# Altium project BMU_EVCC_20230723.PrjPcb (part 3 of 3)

## Sheet BMU_A1_bq79616.SchDoc
size 558 x 431 mm; Date: Not shown in title block; ApprovedBy: Not shown in title block; CheckedBy: Not shown in title block; Author: Not shown in title block; CompanyName: Not shown in title block; Engineer: Not shown in title block; Organization: Not shown in title block; Address1: Not shown in title block; Address2: Not shown in title block; Address3: Not shown in title block; Address4: Not shown in title block; DocumentNumber: 1; Revision: Use project parameter SCH_Rev; SheetNumber: 7; SheetTotal: 9; PageSetup: Record=PageOptions¦CenterHorizontal=True¦CenterVertical=True¦PrintScale=1.00¦XCorrection=1.00¦YCorrection=1.00¦PrintKind=0¦BorderSize=5000000¦LeftOffset=0¦BottomOffset=0¦Orientation=2¦PaperLength=1000¦PaperWidth=1000¦Scale=100¦PaperSource=15¦PrintQuality=600¦MediaType=1¦DitherType=10¦PaperKind=Letter¦PrintScaleMode=1
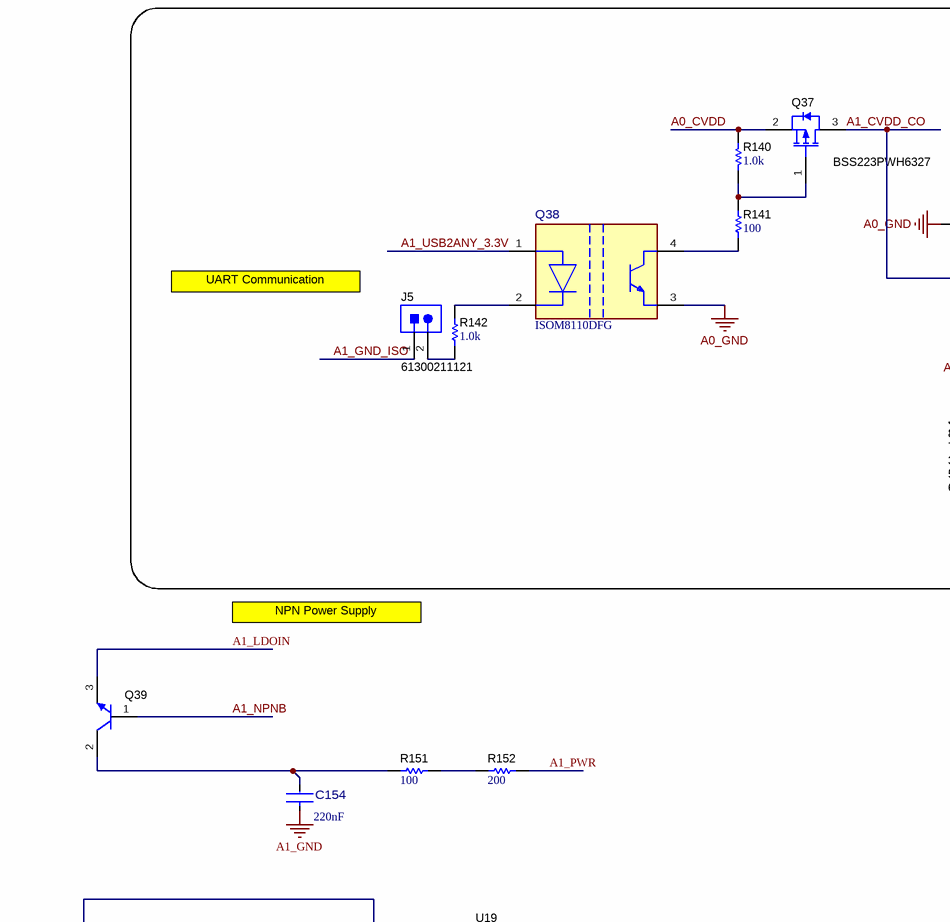
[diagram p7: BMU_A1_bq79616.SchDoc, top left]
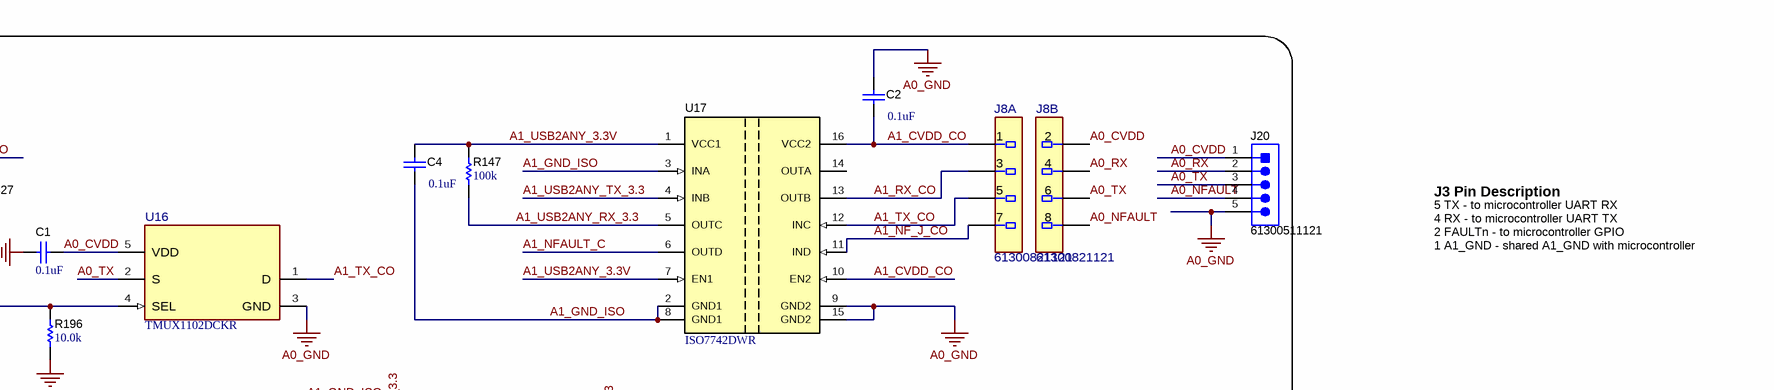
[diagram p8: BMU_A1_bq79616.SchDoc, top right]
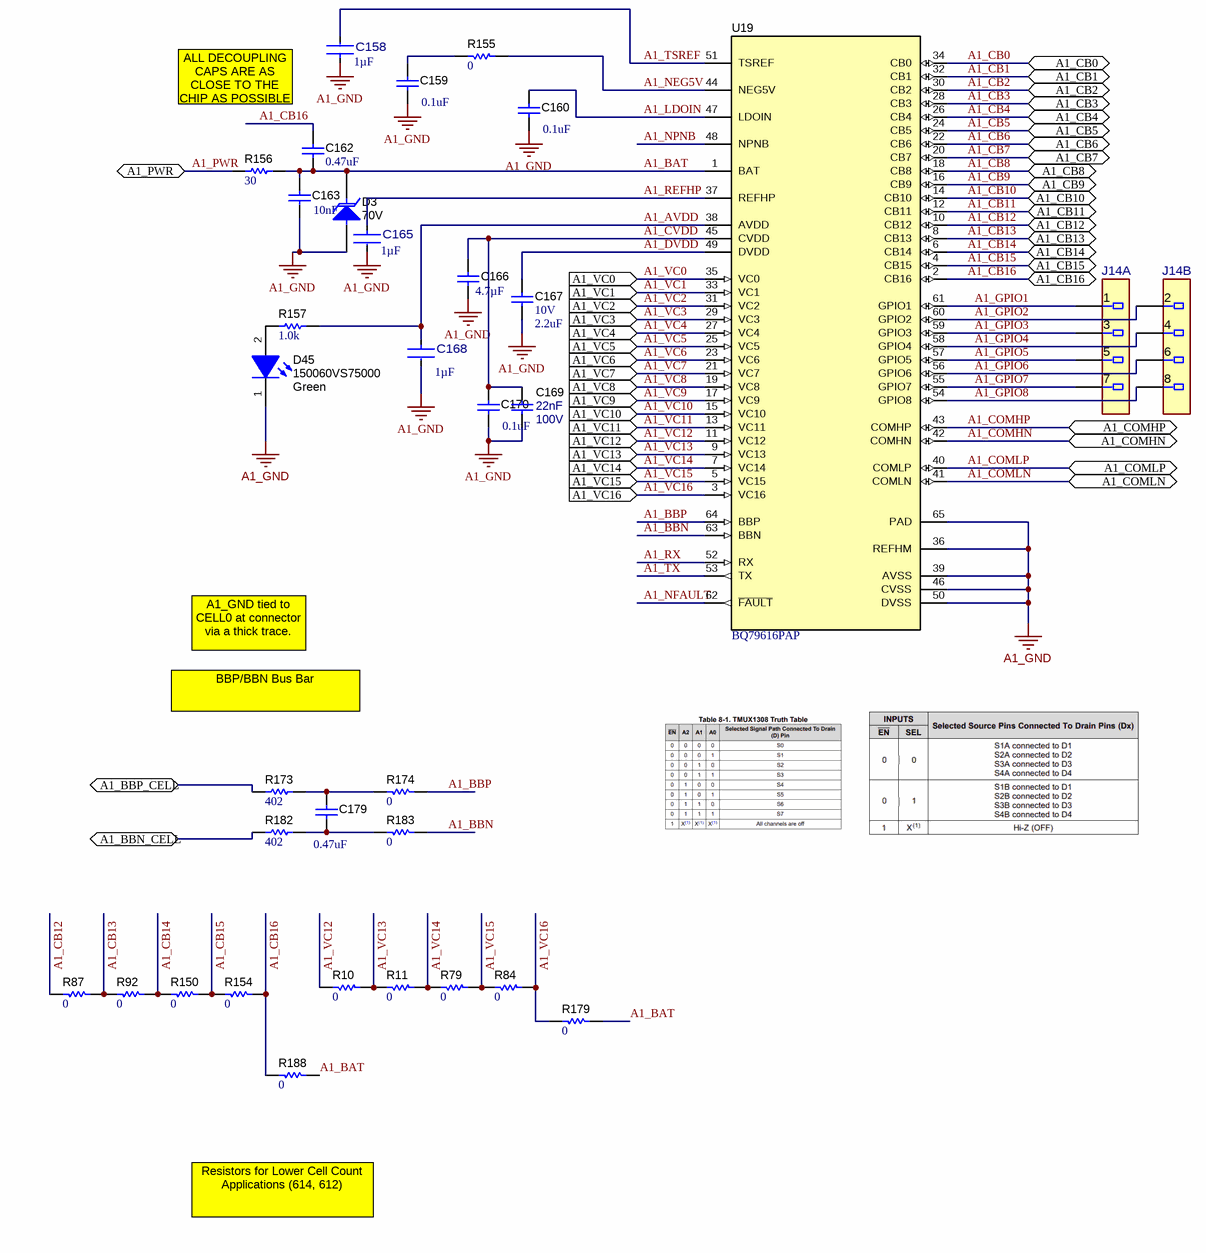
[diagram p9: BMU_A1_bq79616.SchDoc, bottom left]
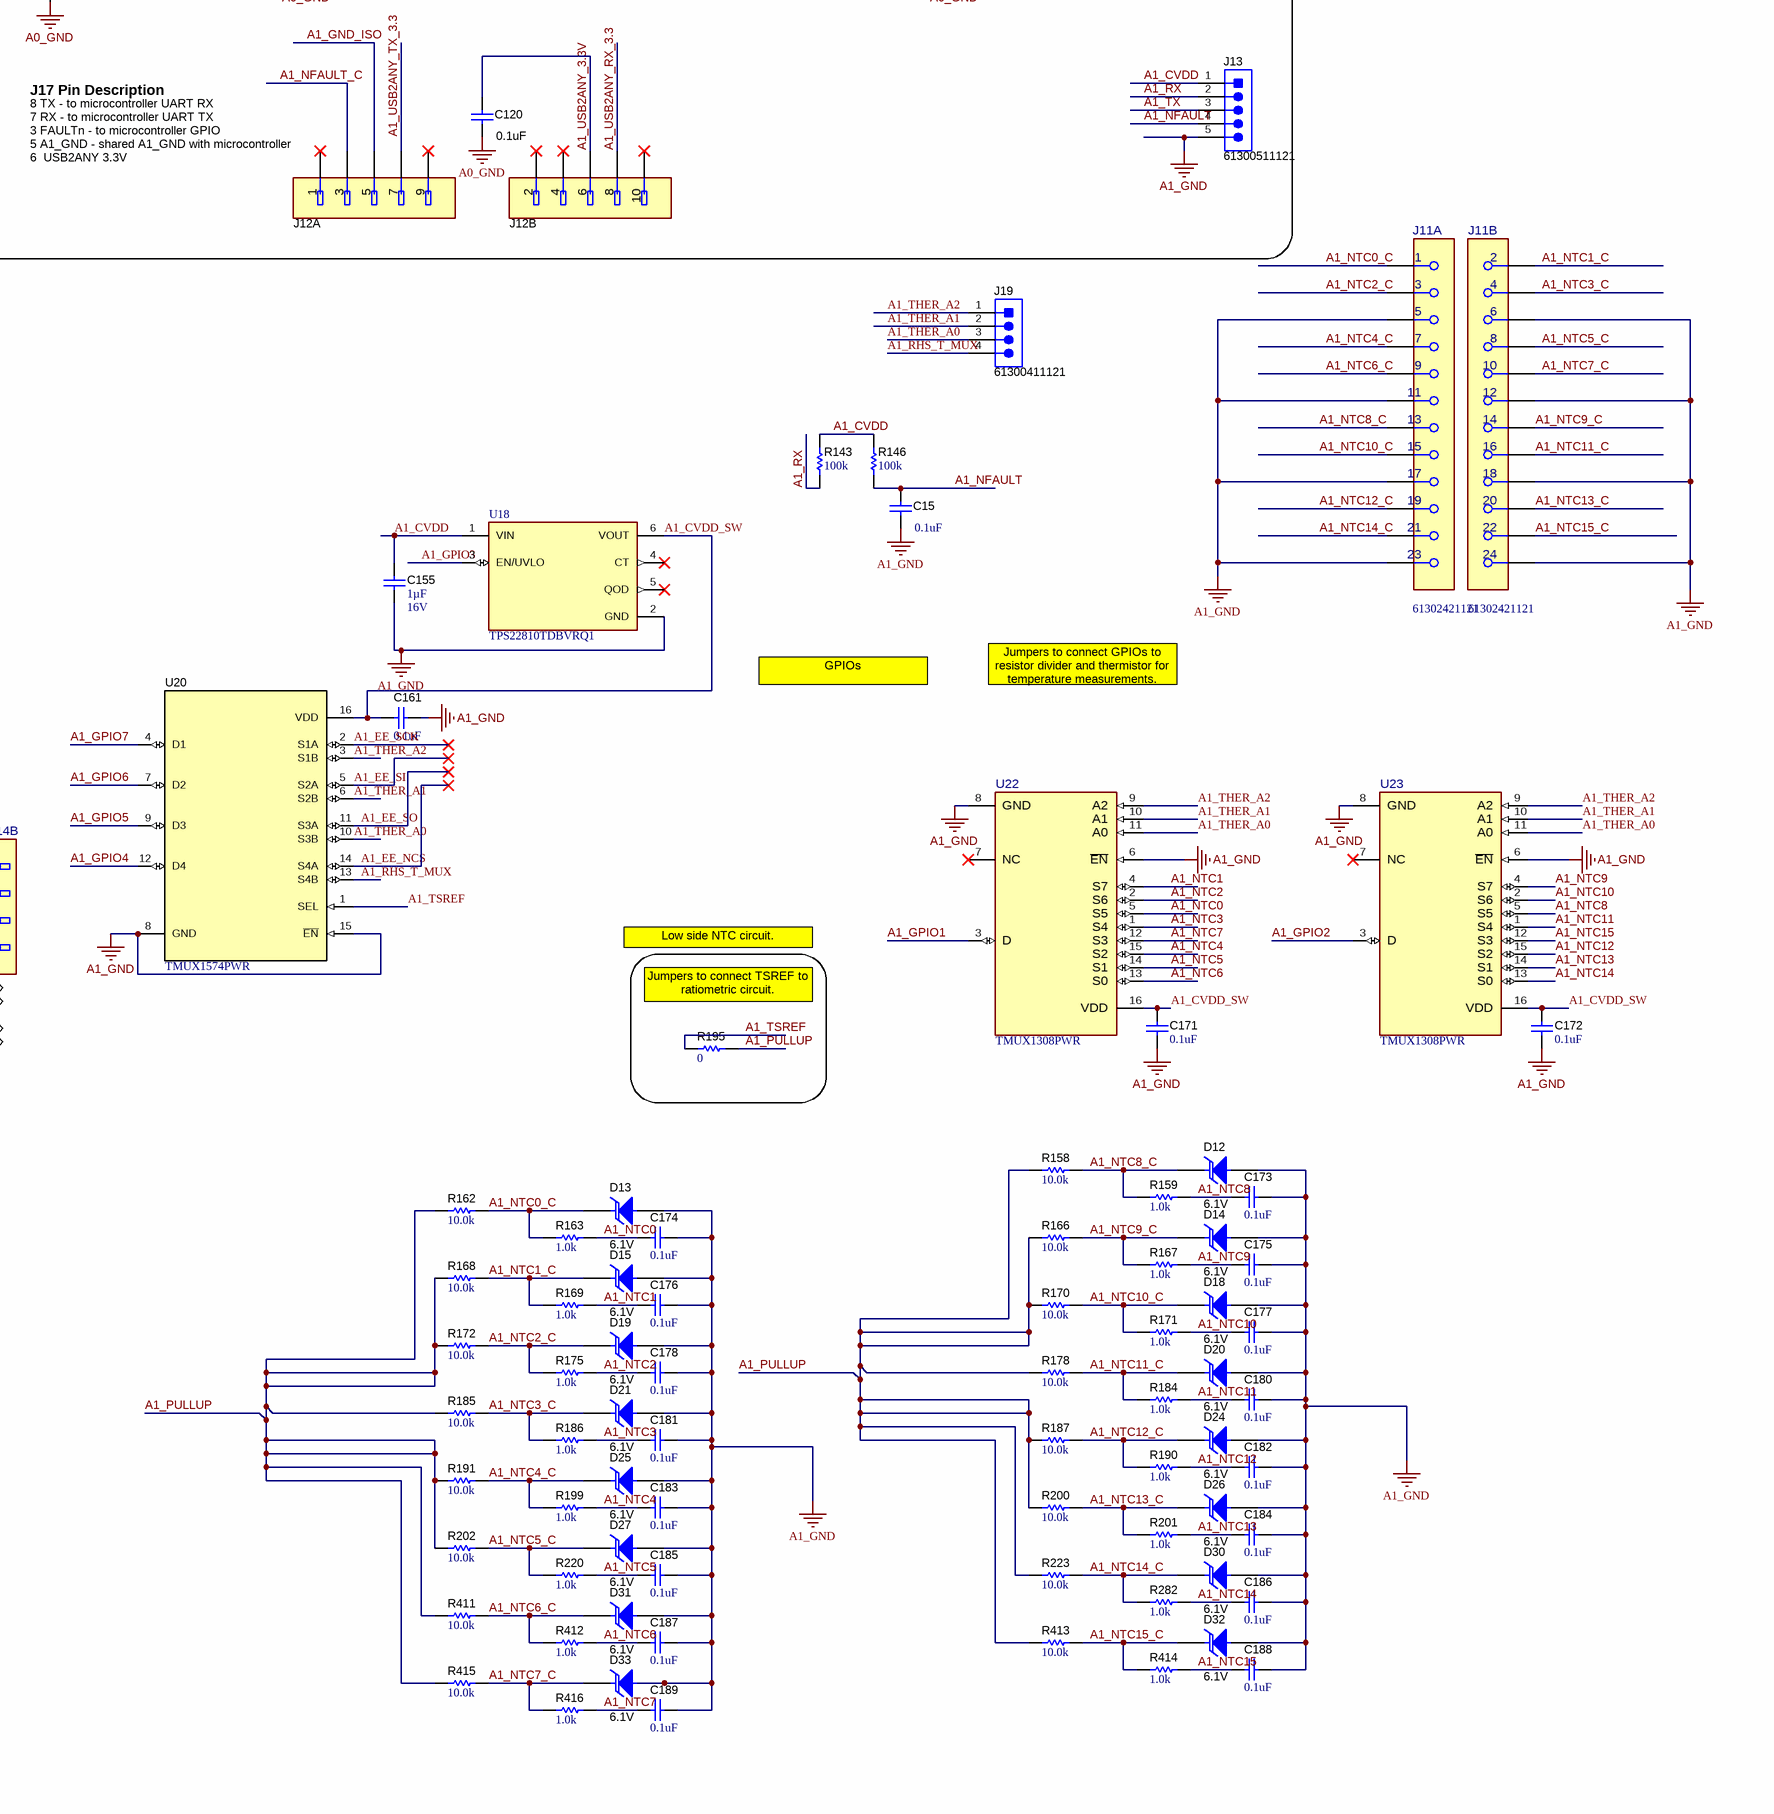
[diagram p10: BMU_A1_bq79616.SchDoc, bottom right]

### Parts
C1  ValueDisplayed: 0.1uF  [0402]  (hidden comment: GCM155R71A104KA55D)
C2  ValueDisplayed: 0.1uF  [0402]  (hidden comment: GCM155R71A104KA55D)
C4  ValueDisplayed: 0.1uF  [0402]  (hidden comment: GCM155R71A104KA55D)
C15  ValueDisplayed: 0.1uF  [0402]  (hidden comment: GCM155R71A104KA55D)
C120  ValueDisplayed: 0.1uF  [0402]  (hidden comment: GCM155R71A104KA55D)
C154  Cap_F: 220nF  [FP-GCM31MR72A224KA37L_1206-MFG]  (hidden comment: GCM31MR72A224KA37L)
C155  Cap_F: 1µF  VDC_V: 16V  [0805_HV]  (hidden comment: GRM21BR71C105KA01L)
C158  Cap_F: 1µF  [FP-C0603C105K8RACAUTO_0603 (1608 Metric)-MFG]  (hidden comment: C0603C105K8RACAUTO)
C159  ValueDisplayed: 0.1uF  [0402]  (hidden comment: GCM155R71A104KA55D)
C160  ValueDisplayed: 0.1uF  [0402]  (hidden comment: GCM155R71A104KA55D)
C161  ValueDisplayed: 0.1uF  [0402]  (hidden comment: GCM155R71H104KE02D)
C162  ValueDisplayed: 0.47uF  [0603]  (hidden comment: GCM188R71C474KA55D)
C163  Cap_F: 10nF  [0603_HV]  (hidden comment: GCM188R72A103KA37J)
C165  Cap_F: 1µF  [FP-C0603C105K8RACAUTO_0603 (1608 Metric)-MFG]  (hidden comment: C0603C105K8RACAUTO)
C166  Cap_F: 4.7µF  [0805_HV]  (hidden comment: C2012X7R1A475M125AC)
C167  VDC_V: 10V  ValueDisplayed: 2.2uF  [0603]  (hidden comment: C0603C225K8PACTU)
C168  Cap_F: 1µF  [FP-C0603C105K8RACAUTO_0603 (1608 Metric)-MFG]  (hidden comment: C0603C105K8RACAUTO)
C169  Cap_F: 22nF  VDC_V: 100V  [0603]  (hidden comment: CGA3E2X7R2A223K080AA)
C170  ValueDisplayed: 0.1uF  [0402]  (hidden comment: GCM155R71A104KA55D)
C171  ValueDisplayed: 0.1uF  [0402]  (hidden comment: GCM155R71H104KE02D)
C172  ValueDisplayed: 0.1uF  [0402]  (hidden comment: GCM155R71H104KE02D)
C173  ValueDisplayed: 0.1uF  [0402]  (hidden comment: GCM155R71H104KE02D)
C174  ValueDisplayed: 0.1uF  [0402]  (hidden comment: GCM155R71H104KE02D)
C175  ValueDisplayed: 0.1uF  [0402]  (hidden comment: GCM155R71H104KE02D)
C176  ValueDisplayed: 0.1uF  [0402]  (hidden comment: GCM155R71H104KE02D)
C177  ValueDisplayed: 0.1uF  [0402]  (hidden comment: GCM155R71H104KE02D)
C178  ValueDisplayed: 0.1uF  [0402]  (hidden comment: GCM155R71H104KE02D)
C179  ValueDisplayed: 0.47uF  [0603]  (hidden comment: GCM188R71C474KA55D)
C180  ValueDisplayed: 0.1uF  [0402]  (hidden comment: GCM155R71H104KE02D)
C181  ValueDisplayed: 0.1uF  [0402]  (hidden comment: GCM155R71H104KE02D)
C182  ValueDisplayed: 0.1uF  [0402]  (hidden comment: GCM155R71H104KE02D)
C183  ValueDisplayed: 0.1uF  [0402]  (hidden comment: GCM155R71H104KE02D)
C184  ValueDisplayed: 0.1uF  [0402]  (hidden comment: GCM155R71H104KE02D)
C185  ValueDisplayed: 0.1uF  [0402]  (hidden comment: GCM155R71H104KE02D)
C186  ValueDisplayed: 0.1uF  [0402]  (hidden comment: GCM155R71H104KE02D)
C187  ValueDisplayed: 0.1uF  [0402]  (hidden comment: GCM155R71H104KE02D)
C188  ValueDisplayed: 0.1uF  [0402]  (hidden comment: GCM155R71H104KE02D)
C189  ValueDisplayed: 0.1uF  [0402]  (hidden comment: GCM155R71H104KE02D)
D3  value 70V  [SMA]  (hidden comment: SMAJ70A)
D12  value 6.1V  [ST0201]  (hidden comment: ESDALC6V1-1U2)
D13  value 6.1V  [ST0201]  (hidden comment: ESDALC6V1-1U2)
D14  value 6.1V  [ST0201]  (hidden comment: ESDALC6V1-1U2)
D15  value 6.1V  [ST0201]  (hidden comment: ESDALC6V1-1U2)
D18  value 6.1V  [ST0201]  (hidden comment: ESDALC6V1-1U2)
D19  value 6.1V  [ST0201]  (hidden comment: ESDALC6V1-1U2)
D20  value 6.1V  [ST0201]  (hidden comment: ESDALC6V1-1U2)
D21  value 6.1V  [ST0201]  (hidden comment: ESDALC6V1-1U2)
D24  value 6.1V  [ST0201]  (hidden comment: ESDALC6V1-1U2)
D25  value 6.1V  [ST0201]  (hidden comment: ESDALC6V1-1U2)
D26  value 6.1V  [ST0201]  (hidden comment: ESDALC6V1-1U2)
D27  value 6.1V  [ST0201]  (hidden comment: ESDALC6V1-1U2)
D30  value 6.1V  [ST0201]  (hidden comment: ESDALC6V1-1U2)
D31  value 6.1V  [ST0201]  (hidden comment: ESDALC6V1-1U2)
D32  value 6.1V  [ST0201]  (hidden comment: ESDALC6V1-1U2)
D33  value 6.1V  [ST0201]  (hidden comment: ESDALC6V1-1U2)
D45  150060VS75000  value Green  [WL-SMCW_GREEN]
J5  61300211121  [WURTH_61300211121]
J8  61300821121  [FP-61300821121_HDR8-MFG]  (parts A,B of 2)
J11  PartNumber: 61302421121  [FP-SSQ-112-04-G-D_CONN_RCPT24-MFG]  (hidden comment: SSQ-112-04-G-D)  (parts A,B of 2)
J12  TSW-105-08-L-D-RA  [FP-TSW-105-08-L-D-RA_HDR10-MFG]  (value not drawn)  (parts A,B of 2)
J13  61300511121  [Wurth_61300511121]
J14  61300821121  [FP-61300821121_HDR8-MFG]  (value not drawn)  (parts A,B of 2)
J19  61300411121  [WURTH_61300411121]
J20  61300511121  [Wurth_61300511121]
Q37  BSS223PWH6327  [SOT-323]
Q38  ISOM8110DFG  [DFG0004A-MFG]
Q39  BJT_NPN_C2B1E3  [DPAK]  (value not drawn)
R10  ValueDisplayed: 0  [0603]  (hidden comment: RC0603JR-070RL)
R11  ValueDisplayed: 0  [0603]  (hidden comment: RC0603JR-070RL)
R79  ValueDisplayed: 0  [0603]  (hidden comment: RC0603JR-070RL)
R84  ValueDisplayed: 0  [0603]  (hidden comment: RC0603JR-070RL)
R87  ValueDisplayed: 0  [0603]  (hidden comment: RC0603JR-070RL)
R92  ValueDisplayed: 0  [0603]  (hidden comment: RC0603JR-070RL)
R140  ValueDisplayed: 1.0k  [0603]  (hidden comment: CRCW06031K00JNEA)
R141  ValueDisplayed: 100  [0603]  (hidden comment: CRCW0603100RJNEA)
R142  ValueDisplayed: 1.0k  [0603]  (hidden comment: CRCW06031K00JNEA)
R143  ValueDisplayed: 100k  [0603]  (hidden comment: CRCW0603100KJNEA)
R146  ValueDisplayed: 100k  [0603]  (hidden comment: CRCW0603100KJNEA)
R147  ValueDisplayed: 100k  [0603]  (hidden comment: Resistor)
R150  ValueDisplayed: 0  [0603]  (hidden comment: RC0603JR-070RL)
R151  ValueDisplayed: 100  [2010]  (hidden comment: CRCW2010100RFKEF)
R152  ValueDisplayed: 200  [2010]  (hidden comment: CRCW2010200RFKEF)
R154  ValueDisplayed: 0  [0603]  (hidden comment: RC0603JR-070RL)
R155  ValueDisplayed: 0  [0603]  (hidden comment: RC0603JR-070RL)
R156  ValueDisplayed: 30  [0805_HV]  (hidden comment: CRCW080530R0JNEA)
R157  ValueDisplayed: 1.0k  [0603]  (hidden comment: CRCW06031K00JNEA)
R158  ValueDisplayed: 10.0k  [0603]  (hidden comment: CRCW060310K0FKEA)
R159  ValueDisplayed: 1.0k  [0402]  (hidden comment: CRCW04021K00JNED)
R162  ValueDisplayed: 10.0k  [0603]  (hidden comment: CRCW060310K0FKEA)
R163  ValueDisplayed: 1.0k  [0402]  (hidden comment: CRCW04021K00JNED)
R166  ValueDisplayed: 10.0k  [0603]  (hidden comment: CRCW060310K0FKEA)
R167  ValueDisplayed: 1.0k  [0402]  (hidden comment: CRCW04021K00JNED)
R168  ValueDisplayed: 10.0k  [0603]  (hidden comment: CRCW060310K0FKEA)
R169  ValueDisplayed: 1.0k  [0402]  (hidden comment: CRCW04021K00JNED)
R170  ValueDisplayed: 10.0k  [0603]  (hidden comment: CRCW060310K0FKEA)
R171  ValueDisplayed: 1.0k  [0402]  (hidden comment: CRCW04021K00JNED)
R172  ValueDisplayed: 10.0k  [0603]  (hidden comment: CRCW060310K0FKEA)
R173  ValueDisplayed: 402  [0603]  (hidden comment: CRCW0603402RFKEA)
R174  ValueDisplayed: 0  [0603]  (hidden comment: RC0603JR-070RL)
R175  ValueDisplayed: 1.0k  [0402]  (hidden comment: CRCW04021K00JNED)
R178  ValueDisplayed: 10.0k  [0603]  (hidden comment: CRCW060310K0FKEA)
R179  ValueDisplayed: 0  [0603]  (hidden comment: RC0603JR-070RL)
R182  ValueDisplayed: 402  [0603]  (hidden comment: CRCW0603402RFKEA)
R183  ValueDisplayed: 0  [0603]  (hidden comment: RC0603JR-070RL)
R184  ValueDisplayed: 1.0k  [0402]  (hidden comment: CRCW04021K00JNED)
R185  ValueDisplayed: 10.0k  [0603]  (hidden comment: CRCW060310K0FKEA)
R186  ValueDisplayed: 1.0k  [0402]  (hidden comment: CRCW04021K00JNED)
R187  ValueDisplayed: 10.0k  [0603]  (hidden comment: CRCW060310K0FKEA)
R188  ValueDisplayed: 0  [0603]  (hidden comment: RC0603JR-070RL)
R190  ValueDisplayed: 1.0k  [0402]  (hidden comment: CRCW04021K00JNED)
R191  ValueDisplayed: 10.0k  [0603]  (hidden comment: CRCW060310K0FKEA)
R195  ValueDisplayed: 0  [0402]  (hidden comment: CRCW04020000Z0ED)
R196  ValueDisplayed: 10.0k  [0603]  (hidden comment: CRCW060310K0FKEA)
R199  ValueDisplayed: 1.0k  [0402]  (hidden comment: CRCW04021K00JNED)
R200  ValueDisplayed: 10.0k  [0603]  (hidden comment: CRCW060310K0FKEA)
R201  ValueDisplayed: 1.0k  [0402]  (hidden comment: CRCW04021K00JNED)
R202  ValueDisplayed: 10.0k  [0603]  (hidden comment: CRCW060310K0FKEA)
R220  ValueDisplayed: 1.0k  [0402]  (hidden comment: CRCW04021K00JNED)
R223  ValueDisplayed: 10.0k  [0603]  (hidden comment: CRCW060310K0FKEA)
R282  ValueDisplayed: 1.0k  [0402]  (hidden comment: CRCW04021K00JNED)
R411  ValueDisplayed: 10.0k  [0603]  (hidden comment: CRCW060310K0FKEA)
R412  ValueDisplayed: 1.0k  [0402]  (hidden comment: CRCW04021K00JNED)
R413  ValueDisplayed: 10.0k  [0603]  (hidden comment: CRCW060310K0FKEA)
R414  ValueDisplayed: 1.0k  [0402]  (hidden comment: CRCW04021K00JNED)
R415  ValueDisplayed: 10.0k  [0603]  (hidden comment: CRCW060310K0FKEA)
R416  ValueDisplayed: 1.0k  [0402]  (hidden comment: CRCW04021K00JNED)
U16  TMUX1102DCKR  [DCK0005A-MFG]
U17  ISO7742DWR  [DW0016B_HV]
U18  TPS22810TDBVRQ1  [FP-DBV0006A-MFG]
U19  PartNumber: BQ79616PAP  [PAP0064F-MFG]  (hidden comment: BQ79616PAPQ1)
U20  TMUX1574PWR  [PW0016A_N]
U22  TMUX1308PWR  [PW0016A-MFG]
U23  TMUX1308PWR  [PW0016A-MFG]

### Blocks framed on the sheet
J17 Pin Description: C1 C2 C4 C120 J5 J8 J12 J13 J20 Q37 Q38 R140-R142 R147 R196 U16 U17

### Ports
A1_BBN_CELL (bidir), A1_BBP_CELL (bidir), A1_CB0 (bidir), A1_CB1 (bidir), A1_CB2 (bidir), A1_CB3 (bidir), A1_CB4 (bidir), A1_CB5 (bidir), A1_CB6 (bidir), A1_CB7 (bidir), A1_CB8 (bidir), A1_CB9 (bidir), A1_CB10 (bidir), A1_CB11 (bidir), A1_CB12 (bidir), A1_CB13 (bidir), A1_CB14 (bidir), A1_CB15 (bidir), A1_CB16 (bidir), A1_COMHN (bidir), A1_COMHP (bidir), A1_COMLN (bidir), A1_COMLP (bidir), A1_PWR (bidir), A1_VC0 (in), A1_VC1 (in), A1_VC2 (in), A1_VC3 (in), A1_VC4 (in), A1_VC5 (in), A1_VC6 (in), A1_VC7 (in), A1_VC8 (in), A1_VC9 (in), A1_VC10 (in), A1_VC11 (in), A1_VC12 (in), A1_VC13 (in), A1_VC14 (in), A1_VC15 (in), A1_VC16 (in)

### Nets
A0_GND: C1.1 C2.2 C120.1 J20.5 Q38.3(Emitter) R196.1 U16.3(GND) U17.9(GND2) U17.15(GND2)
A1_GND: C15.1 C154.1 C155.2 C158.2 C159.1 C160.1 C161.1 C163.2 C165.1 C166.2 C167.1 C168.1 C169.2 C170.1 C171.2 C172.2 C173.2 C174.2 C175.2 C176.2 C177.2 C178.2 C180.2 C181.2 C182.2 C183.2 C184.2 C185.2 C186.2 C187.2 C188.2 C189.2 D3.2(A) D12.2(A) D13.2(A) D14.2(A) D15.2(A) D18.2(A) D19.2(A) D20.2(A) D21.2(A) D24.2(A) D25.2(A) D26.2(A) D27.2(A) D30.2(A) D31.2(A) D32.2(A) D33.2(A) D45.1(K) J11.5 J11.6 J11.11 J11.12 J11.17 J11.18 J11.23 J11.24 J13.5 U18.2(GND) U19.36(REFHM) U19.39(AVSS) U19.46(CVSS) U19.50(DVSS) U19.65(PAD) U20.8(GND) U20.15(~{EN}) U22.6(~{EN}) U22.8(GND) U23.6(~{EN}) U23.8(GND)
A0_CVDD: C1.2 J8.2 J20.1 Q37.2(S) R140.1 U16.5(VDD)
A0_NFAULT: J8.8 J20.4
A0_RX: J8.4 J20.2
A0_TX: J8.6 J20.3 U16.2(S)
A1_AVDD: C168.2 R157.2 U19.38(AVDD)
A1_BAT: C162.2 C163.1 D3.1(K) R156.2 R179.1 R188.1 U19.1(BAT)
A1_BBN: R183.1 U19.63(BBN)
A1_BBN_CELL: R182.1 ; port A1_BBN_CELL
A1_BBP: R174.1 U19.64(BBP)
A1_BBP_CELL: R173.1 ; port A1_BBP_CELL
A1_CB0: U19.34(CB0) ; port A1_CB0
A1_CB1: U19.32(CB1) ; port A1_CB1
A1_CB2: U19.30(CB2) ; port A1_CB2
A1_CB3: U19.28(CB3) ; port A1_CB3
A1_CB4: U19.26(CB4) ; port A1_CB4
A1_CB5: U19.24(CB5) ; port A1_CB5
A1_CB6: U19.22(CB6) ; port A1_CB6
A1_CB7: U19.20(CB7) ; port A1_CB7
A1_CB8: U19.18(CB8) ; port A1_CB8
A1_CB9: U19.16(CB9) ; port A1_CB9
A1_CB10: U19.14(CB10) ; port A1_CB10
A1_CB11: U19.12(CB11) ; port A1_CB11
A1_CB12: R87.2 U19.10(CB12) ; port A1_CB12
A1_CB13: R87.1 R92.2 U19.8(CB13) ; port A1_CB13
A1_CB14: R92.1 R150.2 U19.6(CB14) ; port A1_CB14
A1_CB15: R150.1 R154.2 U19.4(CB15) ; port A1_CB15
A1_CB16: C162.1 R154.1 R188.2 U19.2(CB16) ; port A1_CB16
A1_COMHN: U19.42(COMHN) ; port A1_COMHN
A1_COMHP: U19.43(COMHP) ; port A1_COMHP
A1_COMLN: U19.41(COMLN) ; port A1_COMLN
A1_COMLP: U19.40(COMLP) ; port A1_COMLP
A1_CVDD: C155.1 C166.1 C169.1 C170.2 J13.1 R143.1 R146.1 U18.1(VIN) U19.45(CVDD)
A1_CVDD_CO: C2.1 J8.1 Q37.3(D) R196.2 U16.4(SEL) U17.10(EN2) U17.16(VCC2)
A1_CVDD_SW: C161.2 C171.1 C172.1 U18.6(VOUT) U20.16(VDD) U22.16(VDD) U23.16(VDD)
A1_DVDD: C167.2 U19.49(DVDD)
A1_EE_NCS: U20.14(S4A)
A1_EE_SCK: U20.2(S1A)
A1_EE_SI: U20.5(S2A)
A1_EE_SO: U20.11(S3A)
A1_GND_ISO: C4.1 J5.1 J12.5 U17.2(GND1) U17.3(INA) U17.8(GND1)
A1_GPIO1: J14.1 U19.61(GPIO1) U22.3(D)
A1_GPIO2: J14.2 U19.60(GPIO2) U23.3(D)
A1_GPIO3: J14.3 U18.3(EN/UVLO) U19.59(GPIO3)
A1_GPIO4: J14.4 U19.58(GPIO4) U20.12(D4)
A1_GPIO5: J14.5 U19.57(GPIO5) U20.9(D3)
A1_GPIO6: J14.6 U19.56(GPIO6) U20.7(D2)
A1_GPIO7: J14.7 U19.55(GPIO7) U20.4(D1)
A1_GPIO8: J14.8 U19.54(GPIO8)
A1_LDOIN: C160.2 Q39.3(E) U19.47(LDOIN)
A1_NEG5V: R155.1 U19.44(NEG5V)
A1_NF_J_CO: J8.7 U17.11(IND)
A1_NFAULT: C15.2 J13.4 R146.2 U19.62(~{FAULT})
A1_NFAULT_C: J12.3 U17.6(OUTD)
A1_NPNB: Q39.1(B) U19.48(NPNB)
A1_NTC0: C174.1 R163.2 U22.5(S5)
A1_NTC0_C: D13.1(K) J11.1 R162.2 R163.1
A1_NTC1: C176.1 R169.2 U22.4(S7)
A1_NTC1_C: D15.1(K) J11.2 R168.2 R169.1
A1_NTC2: C178.1 R175.2 U22.2(S6)
A1_NTC2_C: D19.1(K) J11.3 R172.2 R175.1
A1_NTC3: C181.1 R186.2 U22.1(S4)
A1_NTC3_C: D21.1(K) J11.4 R185.2 R186.1
A1_NTC4: C183.1 R199.2 U22.15(S2)
A1_NTC4_C: D25.1(K) J11.7 R191.2 R199.1
A1_NTC5: C185.1 R220.2 U22.14(S1)
A1_NTC5_C: D27.1(K) J11.8 R202.2 R220.1
A1_NTC6: C187.1 R412.2 U22.13(S0)
A1_NTC6_C: D31.1(K) J11.9 R411.2 R412.1
A1_NTC7: C189.1 R416.2 U22.12(S3)
A1_NTC7_C: D33.1(K) J11.10 R415.2 R416.1
A1_NTC8: C173.1 R159.2 U23.5(S5)
A1_NTC8_C: D12.1(K) J11.13 R158.2 R159.1
A1_NTC9: C175.1 R167.2 U23.4(S7)
A1_NTC9_C: D14.1(K) J11.14 R166.2 R167.1
A1_NTC10: C177.1 R171.2 U23.2(S6)
A1_NTC10_C: D18.1(K) J11.15 R170.2 R171.1
A1_NTC11: C180.1 R184.2 U23.1(S4)
A1_NTC11_C: D20.1(K) J11.16 R178.2 R184.1
A1_NTC12: C182.1 R190.2 U23.15(S2)
A1_NTC12_C: D24.1(K) J11.19 R187.2 R190.1
A1_NTC13: C184.1 R201.2 U23.14(S1)
A1_NTC13_C: D26.1(K) J11.20 R200.2 R201.1
A1_NTC14: C186.1 R282.2 U23.13(S0)
A1_NTC14_C: D30.1(K) J11.21 R223.2 R282.1
A1_NTC15: C188.1 R414.2 U23.12(S3)
A1_NTC15_C: D32.1(K) J11.22 R413.2 R414.1
A1_PULLUP: R158.1 R162.1 R166.1 R168.1 R170.1 R172.1 R178.1 R185.1 R187.1 R191.1 R195.2 R200.1 R202.1 R223.1 R411.1 R413.1 R415.1
A1_PWR: R152.2 R156.1 ; port A1_PWR
A1_REFHP: C165.2 U19.37(REFHP)
A1_RHS_T_MUX: J19.4 U20.13(S4B)
A1_RX: J13.2 R143.2 U19.52(RX)
A1_RX_CO: J8.3 U17.13(OUTB)
A1_THER_A0: J19.3 U20.10(S3B) U22.11(A0) U23.11(A0)
A1_THER_A1: J19.2 U20.6(S2B) U22.10(A1) U23.10(A1)
A1_THER_A2: J19.1 U20.3(S1B) U22.9(A2) U23.9(A2)
A1_TSREF: C158.1 R195.1 U19.51(TSREF) U20.1(SEL)
A1_TX: J13.3 U19.53(TX)
A1_TX_CO: J8.5 U16.1(D) U17.12(INC)
A1_USB2ANY_3.3V: C4.2 C120.2 J12.6 Q38.1(AN) R147.1 U17.1(VCC1) U17.7(EN1)
A1_USB2ANY_RX_3.3: J12.8 R147.2 U17.5(OUTC)
A1_USB2ANY_TX_3.3: J12.7 U17.4(INB)
A1_VC0: U19.35(VC0) ; port A1_VC0
A1_VC1: U19.33(VC1) ; port A1_VC1
A1_VC2: U19.31(VC2) ; port A1_VC2
A1_VC3: U19.29(VC3) ; port A1_VC3
A1_VC4: U19.27(VC4) ; port A1_VC4
A1_VC5: U19.25(VC5) ; port A1_VC5
A1_VC6: U19.23(VC6) ; port A1_VC6
A1_VC7: U19.21(VC7) ; port A1_VC7
A1_VC8: U19.19(VC8) ; port A1_VC8
A1_VC9: U19.17(VC9) ; port A1_VC9
A1_VC10: U19.15(VC10) ; port A1_VC10
A1_VC11: U19.13(VC11) ; port A1_VC11
A1_VC12: R10.2 U19.11(VC12) ; port A1_VC12
A1_VC13: R10.1 R11.2 U19.9(VC13) ; port A1_VC13
A1_VC14: R11.1 R79.2 U19.7(VC14) ; port A1_VC14
A1_VC15: R79.1 R84.2 U19.5(VC15) ; port A1_VC15
A1_VC16: R84.1 R179.2 U19.3(VC16) ; port A1_VC16
NetC154_2: C154.2 Q39.2(C) R151.1
NetC159_2: C159.2 R155.2
NetC179_1: C179.1 R173.2 R174.2
NetC179_2: C179.2 R182.2 R183.2
NetD45_2: D45.2(A) R157.1
NetJ5_2: J5.2 R142.1
NetQ37_1: Q37.1(G) R140.2 R141.1
NetQ38_2: Q38.2(CAT) R142.2
NetQ38_4: Q38.4(Collector) R141.2
NetR151_2: R151.2 R152.1

Not connected (* = marked no-connect by the designer): J12 1* 2* 4* 9* 10*; U17 14(OUTA); U18 4(CT)* 5(QOD)*; U22 7(NC)*; U23 7(NC)*

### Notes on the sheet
- J3 Pin Description
- 5 TX - to microcontroller UART RX
- 4 RX - to microcontroller UART TX
- 2 FAULTn - to microcontroller GPIO
- 1 A1_GND - shared A1_GND with microcontroller
- UART Communication
- 8 TX - to microcontroller UART RX
- 7 RX - to microcontroller UART TX
- 3 FAULTn - to microcontroller GPIO
- (near J12) 5 A1_GND - shared A1_GND with microcontroller
- 6  USB2ANY 3.3V
- NPN Power Supply
- ALL DECOUPLING CAPS ARE AS CLOSE TO THE CHIP AS POSSIBLE
- GPIOs
- Jumpers to connect GPIOs to resistor divider and thermistor for temperature measurements.
- Low side NTC circuit.
- (near R195) Jumpers to connect TSREF to ratiometric circuit.
- BBP/BBN Bus Bar
- A1_GND tied to CELL0 at connector via a thick trace.
- Resistors for Lower Cell Count Applications (614, 612)

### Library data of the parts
C1 C2 C4 C15 C159 C160 C170 = CMP-0006350-2: CAP, CERM, 0.1 uF, 10 V, +/- 10%, X7R, AEC-Q200 Grade 1, 0402; Manufacturer: MuRata; TaMin_C: -55°C; Polarized: N; SizeAreaWB_mm2: 3; Value1: Unknown; U/M: EA; Value: 0.1uF; TaMax_C: 125°C; SizeZ_mm: 0.6; SizeX_mm: 1; SizeY_mm: 0.5; Value2: 10V; AEC Qualified: Y; Cap_F: 100nF; AEC Category: Q200
C120 = CMP-0006350-2: CAP, CERM, 0.1 uF, 10 V, +/- 10%, X7R, AEC-Q200 Grade 1, 0402; Manufacturer: MuRata; TaMin_C: -55°C; Polarized: N; SizeAreaWB_mm2: 3; Value1: Unknown; U/M: EA; Value: 0.1uF; TaMax_C: 125°C; SizeZ_mm: 0.6; SizeX_mm: 1; SizeY_mm: 0.5; Value2: 10V; CompType: Capacitor; AEC Qualified: Y; Cap_F: 100nF; AEC Category: Q200
C154 = CMP-0087125-1: Multilayer Ceramic Capacitors MLCC - SMD/SMT 1206 0.22uF 100volts X7R +/-10%; Manufacturer: Murata; TempCo: 15%; Tolerance_%: 10%; SizeZ_mm: 1.25mm; AEC Qualified: Yes; VDC_V: 100V; AEC Grade: Grade 1
C155 = CMP-0008323-2: CAP, CERM, 1 uF, 16 V, +/- 10%, X7R, 0805; Manufacturer: MuRata; TaMin_C: -55°C; ESR_ohm: 3m; Polarized: N; SizeAreaWB_mm2: 6.75; Value1: 0.003 ohm; U/M: EA; Value: 1uF; TaMax_C: 125°C; SizeZ_mm: 1.45; SizeX_mm: 2; SizeY_mm: 1.25; Cap_Case: 0805; SizeArea_mm2: 2.5; AEC Category: Q200
C158 C165 C168 = CMP-0087157-1: CAP CER 0603 1UF 10V X7R 10%; Manufacturer: KEMET; AEC Grade: Grade 1; TempCo: 15%; AEC Qualified: Yes; SizeZ_mm: 0.95mm
C161 C171-C178 C180-C189 = CMP-0006356-2: CAP, CERM, 0.1 uF, 50 V, +/- 10%, X7R, AEC-Q200 Grade 1, 0402; Manufacturer: MuRata; TaMin_C: -55°C; Polarized: N; SizeAreaWB_mm2: 3; Value1: Unknown; U/M: EA; Value: 0.1uF; TaMax_C: 125°C; SizeZ_mm: 0.6; SizeX_mm: 1; SizeY_mm: 0.5; Value2: 50V; AEC Qualified: Y; Cap_F: 100nF; AEC Category: Q200
C162 C179 = CMP-0007138-4: CAP, CERM, 0.47 uF, 16 V, +/- 10%, X7R, AEC-Q200 Grade 1, 0603; Manufacturer: MuRata; Polarized: N; Value: 0.47uF; U/M: EA; Cap_F: 470nF; Value1: Unknown; VDC_V: 16V; TaMin_C: -55°C; TaMax_C: 125°C; AEC Category: Q200; AEC Qualified: Y; AEC Grade: 1; SizeArea_mm2: 1.28; SizeAreaWB_mm2: 4.68; SizeX_mm: 1.6; SizeY_mm: 0.8
C163 = CMP-0084773-1: CAP, CERM, 0.01 µF, 100 V,+/- 10%, X7R, AEC-Q200 Grade 1, 0603; Manufacturer: MuRata; SizeArea_mm2: 1.28; ValueDisplayed: 0.01µF; Polarized: N; AEC Grade: 1; Value2: 100V; SizeY_mm: 0.8; Cap_Case: 0603; TaMax_C: 125°C; Value: 0.01uF; SizeAreaWB_mm2: 4.68; TaMin_C: -55°C; AEC Category: Q200; U/M: EA; AEC Qualified: Y; SizeX_mm: 1.6
C166 = CMP-0007865-2: CAP, CERM, 4.7 uF, 10 V, +/- 20%, X7R, 0805; Manufacturer: TDK; AEC Qualified: N; SizeZ_mm: 1.45; VDC_V: 10V; TaMin_C: -55°C; SizeAreaWB_mm2: 6.75; Value1: Unknown; U/M: EA; Value: 4.7uF; TaMax_C: 125°C; SizeX_mm: 2; SizeY_mm: 1.25; Cap_Case: 0805; SizeArea_mm2: 2.5; AEC Category: Q200
C167 = CMP-0006906-5: CAP, CERM, 2.2 uF, 10 V, +/- 10%, X5R, 0603; Manufacturer: Kemet; TaMin_C: -55°C; Polarized: N; SizeAreaWB_mm2: 4.68; Value1: Unknown; U/M: EA; Value: 2.2uF; TaMax_C: 85°C; SizeZ_mm: 1; SizeX_mm: 1.6; SizeY_mm: 0.8; SizeArea_mm2: 1.28; Cap_F: 2.2µF; AEC Category: Q200
C169 = CMP-0007086-4: CAP, CERM, 0.022 uF, 100 V, +/- 10%, X7R, AEC-Q200 Grade 1, 0603; Manufacturer: TDK; TaMin_C: -55°C; ESR_ohm: 0.083542; Polarized: N; SizeAreaWB_mm2: 4.68; Value1: 0.083542 ohm; U/M: EA; TaMax_C: 125°C; SizeZ_mm: 1; SizeX_mm: 1.6; SizeY_mm: 0.8; SizeArea_mm2: 1.28; AEC Qualified: Y; IRMS_A: 6.09312dA; AEC Category: Q200
D3 = CMP-0084973-1: Diode, TVS, Uni, 70 V, 113 Vc, 400 W, 3.5 A, SMA; Manufacturer: Wurth Elektronik; PartNumber: 824500701; Vc: 113V; SizeY_mm: 2.92; RJA_CperW: 120; Ppk: 400W; SizeZ_mm: 2.87; AEC Qualified: N; Vbr_Min: 77.8V; SizeAreaWB_mm2: 37.3428; Ipp: 3.5A; SizeArea_mm2: 16.3228; AEC Category: Q101; SizeX_mm: 5.59; Vbr_Max: 86V
D12-D15 D18-D21 D24-D27 D30-D33 = CMP-0006069-3: Diode, TVS, Uni, 6.1 V, 0201; Manufacturer: Texas Instruments; PartNumber: ESD441DPLR; SizeX_mm: 0.6; Ppk: 20W; SizeY_mm: 0.3; Ipp: 2A; SizeAreaWB_mm2: 2.08; SizeArea_mm2: 0.18; Vbr_Max: 8V; AEC Qualified: N; SizeZ_mm: 0.33; AEC Category: Q101
D45 = CMP-0002894-2: LED, Green, SMD; Manufacturer: Wurth Elektronik; Type: AlInGaP; Value2: 2V; Io_A: 20mA; Value1: W
J5 = CMP-0054794-2: Header, 2.54 mm, 2x1, Gold, TH; Manufacturer: Wurth Elektronik; Shrouded: N; Gender: Male; Green_REACh: Passed; Pitch_mm: 2.54; Green_Lifecycle: Active; Row_Count: 1; Cert_UL: Y
J8 J14 = CMP-0087153-1: CONN HEADER VERT 8POS 2.54MM; Manufacturer: Wurth Elektronik; Voltage_V: 250V; Row_Count: 2; Current_A: 3A; ContactFinish: Gold
J11 = CMP-0096812-1: 24 Position Receptacle Connector 0.100" (2.54mm) Through Hole Gold; Manufacturer: Wurth Elektronik; Conn Orientation: Vertical; ContactFinish: Gold,Nickel; SizeZ_mm: 8.64mm; AEC Qualified: No; Voltage_V: 655V; Conn Gender: Female; Is Female: yes; Row_Count: 2
J12 = CMP-0086439-1: CONN HEADER 10POS .100 DL R/A AU; Manufacturer: Wurth Elektronik; PartNumber: 61301021021; Row_Count: 2; Voltage_V: 550V; ContactFinish: Gold,Nickel; Current_A: 6.3A; Symbol Name: SYM-TSW-105-08-L-D-RA
J13 J20 = CMP-0084909-1: Header, 2.54mm, 5x1, Gold, TH; Manufacturer: Wurth Elektronik; Pitch_mm: 2.54; Gender: Male; Row_Count: 1; Shrouded: N; Current_A: 3A; Voltage_V: 250V
J19 = CMP-0054798-2: Header, 2.54 mm, 4x1, Gold, TH; Manufacturer: Wurth Elektronik; Pitch_mm: 2.54; Gender: Male; Row_Count: 1; Cert_UL: Y; Shrouded: N
Q37 = CMP-0000010-3: MOSFET, P-CH, -20 V, -0.39 A, SOT-323; Alternate Manufacturer: None; Manufacturer: Infineon Technologies; Value: -20V; Rdson45_ohm: 1.2; SizeX_mm: 2.2; AEC Category: Q101; ChMode: Enhancement; Vgs_V: -12V; Value1: 1; IdsMax_A: -390mA; ChType: P; SizeAreaWB_mm2: 10.24; QgTyp_nC: -0.5; SizeArea_mm2: 4.84; SizeZ_mm: 1.1
Q38 = CMP-0098363-1: 3.75-kVRMS, Single-Channel Opto-Emulator with Transistor Output; Manufacturer: Texas Instruments; SizeZ_mm: 2.65mm; AEC Qualified: No; CTR (Max): 160%; CTR (Min): 80%; Emiiter Collector Voltage: 7V; Forward Current: 10mA; Power_TotalModule: 200mW; Standoff Height: 0.05mm; TaMax_C: +125°C; TaMin_C: -55°C; TJmax_C: +150°C; Turn Off Delay Time: 5us; Turn On Delay Time: 1.7us; Value: 80V; Vf_V: 1.1V; Voltage_Isolation_Vrms: 3750Vrms
Q39 = CMP-0000504-4: Transistor, NPN, 150 V, 1 A, AEC-Q101, DPAK; Manufacturer: Diodes Inc.; PartNumber: ZXTN4004KTC; CompType: BJT; IcRated_A: 1A; PNP: 0; SizeArea_mm2: 64.8114; TaMax_C: 150°C; Vceo_V: 150V; TaMin_C: -55°C; SizeX_mm: 9.91; SizeY_mm: 6.54; SizeZ_mm: 2.29; Value1: 1 A; AEC Category: Q101; Vcesat1_V: 250mV; NPN: 1; SizeAreaWB_mm2: 101.7114; AEC Qualified: Y; Value: 150 V
R10 R11 R79 R84 R87 R92 R150 R154 R155 R174 R179 R183 R188 = CMP-0025885-5: RES, 0, 5%, 0.1 W, 0603; Manufacturer: Yageo; Power_W: 100mW; TempCo: 200 ppm/C; Value_Code: 0000; Value: 0; EIA_Code: E24; SizeX_mm: 1.6; SizeY_mm: 0.8; SizeZ_mm: 1; Value2: 0.1W; SizeArea_mm2: 1.28; AEC Qualified: N; VDC_V: 75V; AEC Category: Q200; SizeAreaWB_mm2: 4.68
R140 R142 = CMP-0025729-4: RES, 1.0 k, 5%, 0.1 W, AEC-Q200 Grade 0, 0603; Manufacturer: Vishay-Dale; Power_W: 100mW; TempCo: 200 ppm/C; Value_Code: 1k00; Value: 1.0k; EIA_Code: E24; Res_ohm: 1k; SizeX_mm: 1.6; SizeY_mm: 0.8; SizeZ_mm: 1; Value2: 0.1W; SizeArea_mm2: 1.28; AEC Qualified: Y; VDC_V: 75V; AEC Category: Q200; AEC Grade: 0
R141 = CMP-0025700-4: RES, 100, 5%, 0.1 W, AEC-Q200 Grade 0, 0603; Manufacturer: Vishay-Dale; Power_W: 100mW; TempCo: 200 ppm/C; Value_Code: 100R; Value: 100; EIA_Code: E24; SizeX_mm: 1.6; SizeY_mm: 0.8; SizeZ_mm: 1; Value2: 0.1W; SizeArea_mm2: 1.28; AEC Qualified: Y; VDC_V: 75V; AEC Category: Q200; AEC Grade: 0
R143 R146 = CMP-0025698-4: RES, 100 k, 5%, 0.1 W, AEC-Q200 Grade 0, 0603; Manufacturer: Vishay-Dale; VDC_V: 75V; Power_W: 100mW; Value: 100k; Value2: 0.1W; EIA_Code: E24; TempCo: 200 ppm/C; SizeX_mm: 1.6; SizeY_mm: 0.8; SizeZ_mm: 1; SizeArea_mm2: 1.28; AEC Qualified: Y; AEC Category: Q200; AEC Grade: 0
R147 = CMP-0025698-4: RES, 100 k, 5%, 0.1 W, AEC-Q200 Grade 0, 0603; Manufacturer: Vishay-Dale; PartNumber: CRCW0603100KJNEA; VDC_V: 75V; Power_W: 100mW; Value: 100k; Value2: 0.1W; EIA_Code: E24; TempCo: 200 ppm/C; SizeX_mm: 1.6; SizeY_mm: 0.8; SizeZ_mm: 1; SizeArea_mm2: 1.28; AEC Qualified: Y; AEC Category: Q200; AEC Grade: 0
R151 = CMP-0016209-3: RES, 100, 1%, 0.75 W, AEC-Q200 Grade 0, 2010; Manufacturer: Vishay-Dale; Power_W: 750mW; TempCo: 100 ppm/C; Value_Code: 100R; Value: 100; EIA_Code: E96; SizeX_mm: 5; SizeY_mm: 2.5; SizeZ_mm: 1.66; Value2: 0.75W; SizeArea_mm2: 12.5; AEC Qualified: Y; VDC_V: 400V; AEC Category: Q200; AEC Grade: 0
R152 = CMP-0016302-3: RES, 200, 1%, 0.75 W, AEC-Q200 Grade 0, 2010; Manufacturer: Vishay-Dale; Power_W: 750mW; TempCo: 100 ppm/C; Value_Code: 200R; Value: 200; EIA_Code: E96; SizeX_mm: 5; SizeY_mm: 2.5; SizeZ_mm: 1.66; Value2: 0.75W; SizeArea_mm2: 12.5; AEC Qualified: Y; VDC_V: 400V; AEC Category: Q200; AEC Grade: 0
R156 = CMP-0020525-3: RES, 30, 5%, 0.125 W, AEC-Q200 Grade 0, 0805; Manufacturer: Vishay-Dale; Power_W: 125mW; TempCo: 200 ppm/C; Value_Code: 30R0; Value: 30; EIA_Code: E24; SizeX_mm: 2; SizeY_mm: 1.25; SizeZ_mm: 1.45; Value2: 0.125W; SizeArea_mm2: 2.5; AEC Qualified: Y; VDC_V: 150V; AEC Category: Q200; AEC Grade: 0
R157 = CMP-0025729-4: RES, 1.0 k, 5%, 0.1 W, AEC-Q200 Grade 0, 0603; Manufacturer: Vishay-Dale; Value: 1.0k; Res_ohm: 1k; Value_Code: 1k00; Power_W: 100mW; Value2: 0.1W; VDC_V: 75V; TempCo: 200 ppm/C; EIA_Code: E24; SizeArea_mm2: 1.28; SizeX_mm: 1.6; SizeY_mm: 0.8; SizeZ_mm: 1; AEC Category: Q200; AEC Qualified: Y; AEC Grade: 0
R158 R162 R166 R168 R170 R172 R178 R185 R187 R191 R196 R200 R202 R223 R411 R413 R415 = CMP-0021998-4: RES, 10.0 k, 1%, 0.1 W, AEC-Q200 Grade 0, 0603; Manufacturer: Vishay-Dale; Power_W: 100mW; TempCo: 100 ppm/C; Value_Code: 10k0; Value: 10.0k; EIA_Code: E96; Res_ohm: 10k; SizeX_mm: 1.6; SizeY_mm: 0.8; SizeZ_mm: 1; Value2: 0.1W; SizeArea_mm2: 1.28; AEC Qualified: Y; VDC_V: 75V; AEC Category: Q200; AEC Grade: 0
R159 R163 R167 R169 R171 R175 R184 R186 R190 R199 R201 R220 R282 R412 R414 R416 = CMP-0026852-3: RES, 1.0 k, 5%, 0.063 W, AEC-Q200 Grade 0, 0402; Manufacturer: Vishay-Dale; Power_W: 63mW; TempCo: 200 ppm/C; Value_Code: 1k00; Value: 1.0k; EIA_Code: E24; Res_ohm: 1k; SizeX_mm: 1; SizeY_mm: 0.5; SizeZ_mm: 0.6; Value2: 0.063W; AEC Qualified: Y; VDC_V: 50V; AEC Category: Q200; AEC Grade: 0
R173 R182 = CMP-0022409-5: RES, 402, 1%, 0.1 W, AEC-Q200 Grade 0, 0603; Manufacturer: Vishay-Dale; Power_W: 100mW; TempCo: 100 ppm/C; Value_Code: 402R; Value: 402; EIA_Code: E96; SizeX_mm: 1.6; SizeY_mm: 0.8; SizeZ_mm: 1; Value2: 0.1W; SizeArea_mm2: 1.28; AEC Qualified: Y; VDC_V: 75V; AEC Grade: 0; AEC Category: Q200
R195 = CMP-0026822-3: RES, 0, 5%, 0.063 W, AEC-Q200 Grade 0, 0402; Manufacturer: Vishay-Dale; Power_W: 63mW; TempCo: 200 ppm/C; Value_Code: 0000; Value: 0; EIA_Code: E24; SizeX_mm: 1; SizeY_mm: 0.5; SizeZ_mm: 0.6; Value2: 0.063W; AEC Qualified: Y; VDC_V: 50V; AEC Category: Q200
U16 = CMP-0094645-1: Analog Switch ICs 3-pA on-state leakage current, 5-V, 1:1 (SPST), 1-channel precision switch (active high) 5-SC70 -40 to 125; Manufacturer: Texas Instruments; Min Supply Voltage: 1.08V; AEC Qualified: No; TaMin_C: -40°C; -3Db Bandwith: 300MHz; Nominal Supply Current: 0.003uA; On State Resistance: 1.8Ω; Max Supply Voltage: 5.5V; PositionCount: 1; Standoff Height: 0mm; SizeZ_mm: 1.1mm; TaMax_C: +125°C; TJmax_C: +150°C
U17 = CMP-0078444-2: High-Speed, Low-Power, Robust EMC Quad-Channel Digital Isolator, DW0016B (SOIC-16); Manufacturer: Texas Instruments; SizeAreaWB_mm2: 152.52; Rating: Catalog; SizeArea_mm2: 107.12; AEC Qualified: N; CompType: IC; AEC Category: Q200; SizeY_mm: 10.3; SizeX_mm: 10.4; SizeZ_mm: 2.65
U18 = CMP-04910-000007-1: IC PWR SWITCH N-CHAN 1:1 SOT23-6; Manufacturer: Texas Instruments; Max Supply Voltage: 18V; Standoff Height: 0mm; Nominal Supply Current: 49-62uA; Automotive Grade: Grade 2; Min Supply Voltage: 2.7V; Max Junction Temp: +150°C; Number Of Outputs: 1
U19 = CMP-0750035-3: SafeTI™ Precision Monitor With Integrated Hardware Protector for Lithium-Ion, Lithium Phosphate, Lithium Titanate Battery Pack, PAP0064F (HTQFP-64); Manufacturer: Texas Instruments; SizeX_mm: 12; SizeArea_mm2: 144; SizeAreaWB_mm2: 196; AEC Qualified: Y; SizeZ_mm: 1.2; AEC Category: Q200; CompType: IC
U20 = CMP-0086166-2: Low-capacitance, 2:1 (SPDT) 4-channel, powered-off protection switch with 1.8 V logic, PW0016A (TSSOP-16); Alternate Manufacturer: Texas Instruments; AEC Qualified: N; Rating: Catalog; SizeZ_mm: 1.2; CompType: IC; SizeArea_mm2: 32; AEC Category: Q200; SizeY_mm: 5; SizeAreaWB_mm2: 58.8; SizeX_mm: 6.4
U22 U23 = CMP-0090991-1: 5-V, 8: 1, 1-channel general-purpose multiplexer with 1.8-V logic control 16-TSSOP -40 to 125; Manufacturer: Texas Instruments; Max Supply Voltage: 5.5V; AEC Qualified: No; PositionCount: 1; Min Supply Voltage: 1.62V; -3Db Bandwith: 350-500MHz; Mux Demux Ratio: 8:1; Nominal Supply Current: 1uA; SizeZ_mm: 1.2mm; TaMin_C: -40°C; TaMax_C: +125°C; Standoff Height: 0.05mm; TJmax_C: +150°C; On State Resistance: 75-650Ω

## Sheet BMU0912_Hardware.SchDoc
size C; SheetNumber: 6; SheetTotal: 9
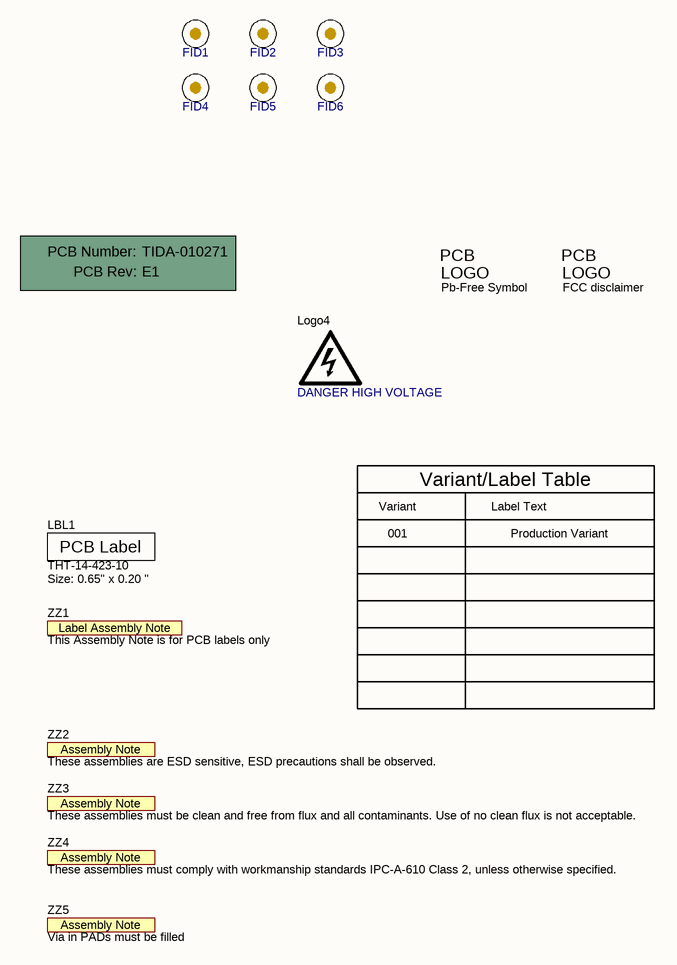
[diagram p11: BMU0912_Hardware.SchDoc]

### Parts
!PCB1  Printed Circuit Board  (value not drawn)  (mechanical)
FID1  Fiducial  [Fiducial10-30]  (value not drawn)
FID2  Fiducial  [Fiducial10-30]  (value not drawn)
FID3  Fiducial  [Fiducial10-30]  (value not drawn)
FID4  Fiducial  [Fiducial10-30]  (value not drawn)
FID5  Fiducial  [Fiducial10-30]  (value not drawn)
FID6  Fiducial  [Fiducial10-30]  (value not drawn)
LBL1  THT-14-423-10  Note: Size: 0.65" x 0.20 "  [Label_650x200]
Logo2  Pb-Free Symbol  [Pb-Free_Overlay_Small]  (no BOM)
Logo3  FCC disclaimer  [FCC_disclaimer]  (no BOM)
Logo4  DANGER HIGH VOLTAGE  [IEC_HighVoltage_Small]  (no BOM)
ZZ1  This Assembly Note is for PCB labels only  [AssemblyNoteLabel]  (no BOM)
ZZ2  These assemblies are ESD sensitive, ESD precautions shall be observed.  [AssemblyNote]  (no BOM)
ZZ3  These assemblies must be clean and free from flux and all contaminants. Use of no clean flux is not acceptable.  [AssemblyNote]  (no BOM)
ZZ4  These assemblies must comply with workmanship standards IPC-A-610 Class 2, unless otherwise specified.  [AssemblyNote]  (no BOM)
ZZ5  Via in PADs must be filled  [AssemblyNote]  (no BOM)

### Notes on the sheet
- Variant/Label Table
- Variant
- 001
- Label Text
- Production Variant

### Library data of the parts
!PCB1 = CMP-0003618-2: Manufacturer: Any; PartNumber: TIDA-010271
FID1-FID6 = CMP-0077181-1: Fiducial mark.  There is nothing to buy or mount.
LBL1 = CMP-0003625-1: Thermal Transfer Printable Labels, 0.650" W x 0.200" H - 10,000 per roll; Manufacturer: Brady; CompType: Label
Logo2 = CMP-0074839-1: SymbolCreator: a0412235; Library Reference: Logo
Logo3 = CMP-0074847-1: FCC_disclaimer; Library Reference: Logo
Logo4 = CMP-0074835-1: IEC 61010-1 High Voltage Warning; SymbolCreator: a0412235
ZZ1 = CMP-0003616-3
ZZ2 = CMP-0077236-1
ZZ3 = CMP-0077237-1
ZZ4 = CMP-0077238-1
ZZ5 = CMP-0077238-1: These assemblies must comply with workmanship standards IPC-A-610 Class 2, unless otherwise specified.

## Sheet Cell_Simulator.SchDoc
size A3; Date: Not shown in title block; ApprovedBy: Not shown in title block; CheckedBy: Not shown in title block; Author: Not shown in title block; CompanyName: Not shown in title block; Engineer: Not shown in title block; Organization: Not shown in title block; Address1: Not shown in title block; Address2: Not shown in title block; Address3: Not shown in title block; Address4: Not shown in title block; DocumentNumber: 1; Revision: Use project parameter SCH_Rev; SheetNumber: 9; SheetTotal: 9; PageSetup: Record=PageOptions¦CenterHorizontal=True¦CenterVertical=True¦PrintScale=0.69¦XCorrection=1.00¦YCorrection=1.00¦PrintKind=0¦BorderSize=5000000¦LeftOffset=0¦BottomOffset=0¦Orientation=2¦PaperLength=1000¦PaperWidth=1000¦Scale=100¦PaperSource=15¦PrintQuality=600¦MediaType=1¦DitherType=10¦PaperKind=Letter¦PrintScaleMode=1
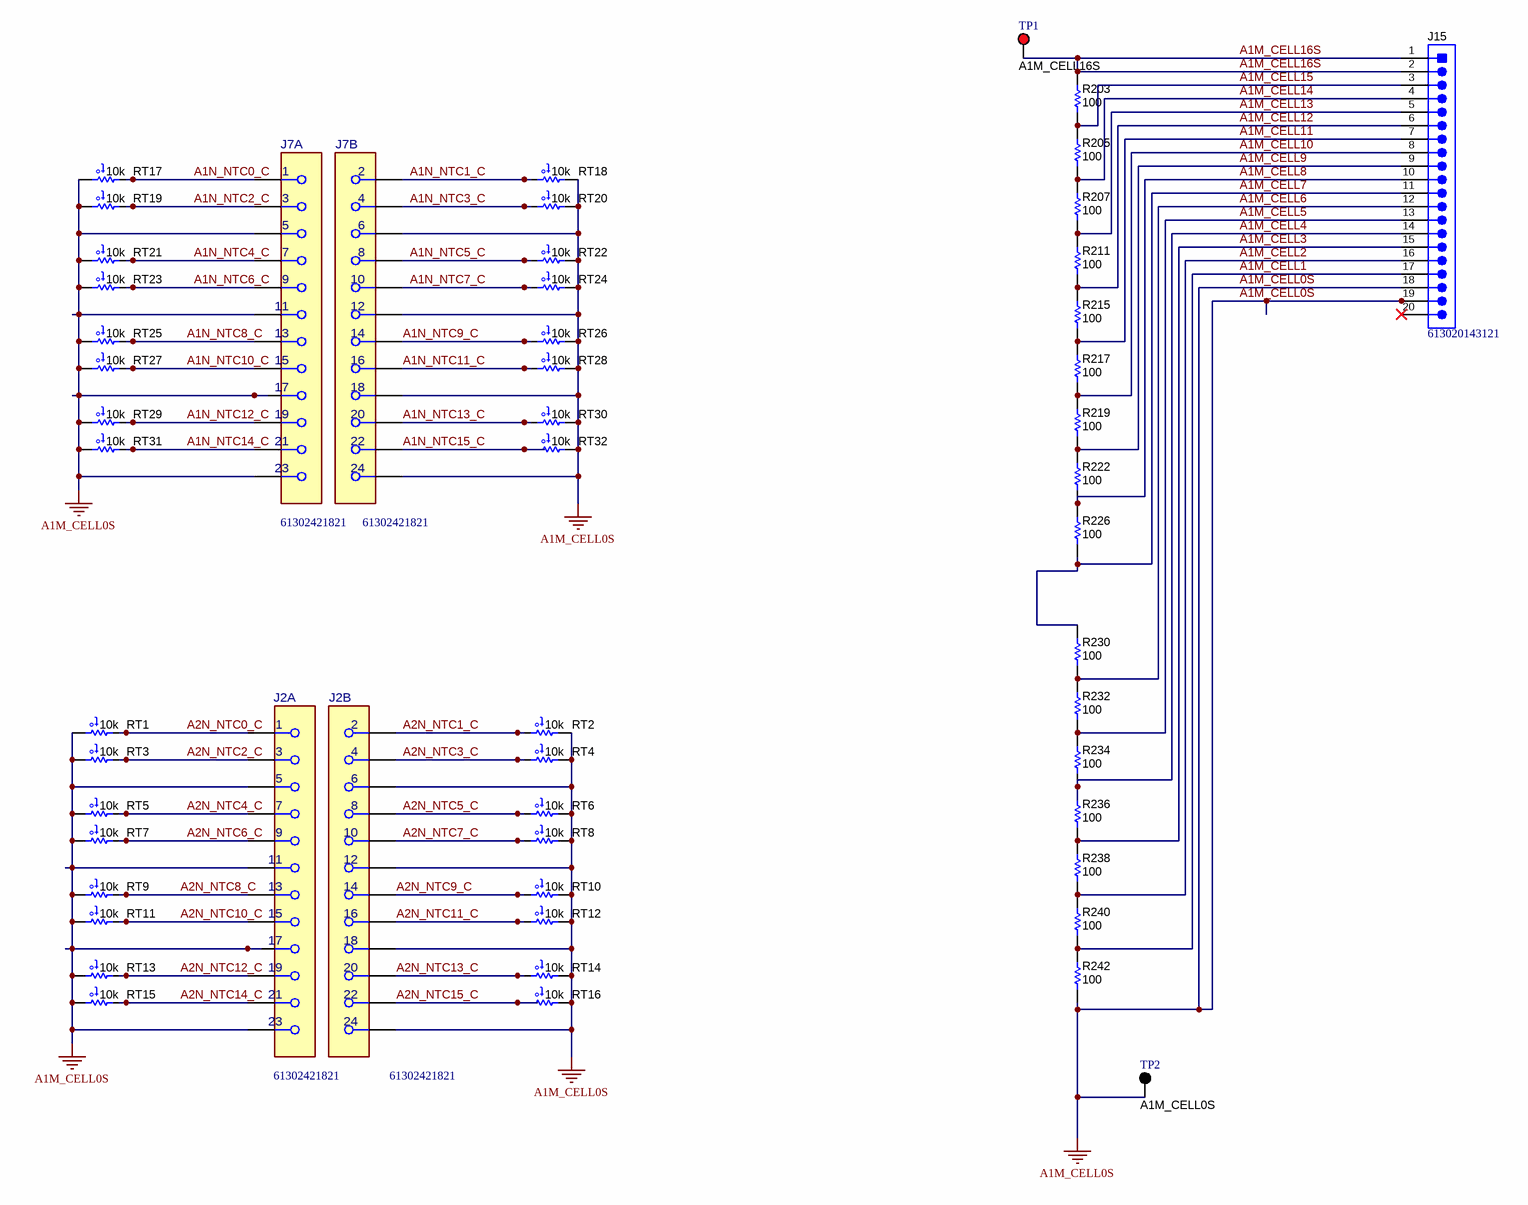
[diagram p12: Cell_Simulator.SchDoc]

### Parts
J2  61302421821  [FP-SSQ-112-04-G-D_CONN_RCPT24-MFG]  (parts A,B of 2)
J7  61302421821  [FP-SSQ-112-04-G-D_CONN_RCPT24-MFG]  (parts A,B of 2)
J15  613020143121  [TSW-120-07-G-S]
R203  ValueDisplayed: 100  [2512]  (hidden comment: CRCW2512100RFKEG)
R205  ValueDisplayed: 100  [2512]  (hidden comment: CRCW2512100RFKEG)
R207  ValueDisplayed: 100  [2512]  (hidden comment: CRCW2512100RFKEG)
R211  ValueDisplayed: 100  [2512]  (hidden comment: CRCW2512100RFKEG)
R215  ValueDisplayed: 100  [2512]  (hidden comment: CRCW2512100RFKEG)
R217  ValueDisplayed: 100  [2512]  (hidden comment: CRCW2512100RFKEG)
R219  ValueDisplayed: 100  [2512]  (hidden comment: CRCW2512100RFKEG)
R222  ValueDisplayed: 100  [2512]  (hidden comment: CRCW2512100RFKEG)
R226  ValueDisplayed: 100  [2512]  (hidden comment: CRCW2512100RFKEG)
R230  ValueDisplayed: 100  [2512]  (hidden comment: CRCW2512100RFKEG)
R232  ValueDisplayed: 100  [2512]  (hidden comment: CRCW2512100RFKEG)
R234  ValueDisplayed: 100  [2512]  (hidden comment: CRCW2512100RFKEG)
R236  ValueDisplayed: 100  [2512]  (hidden comment: CRCW2512100RFKEG)
R238  ValueDisplayed: 100  [2512]  (hidden comment: CRCW2512100RFKEG)
R240  ValueDisplayed: 100  [2512]  (hidden comment: CRCW2512100RFKEG)
R242  ValueDisplayed: 100  [2512]  (hidden comment: CRCW2512100RFKEG)
RT1  value 10k  [0603S]  (hidden comment: ERT-J1VG103GA)
RT2  value 10k  [0603S]  (hidden comment: ERT-J1VG103GA)
RT3  value 10k  [0603S]  (hidden comment: ERT-J1VG103GA)
RT4  value 10k  [0603S]  (hidden comment: ERT-J1VG103GA)
RT5  value 10k  [0603S]  (hidden comment: ERT-J1VG103GA)
RT6  value 10k  [0603S]  (hidden comment: ERT-J1VG103GA)
RT7  value 10k  [0603S]  (hidden comment: ERT-J1VG103GA)
RT8  value 10k  [0603S]  (hidden comment: ERT-J1VG103GA)
RT9  value 10k  [0603S]  (hidden comment: ERT-J1VG103GA)
RT10  value 10k  [0603S]  (hidden comment: ERT-J1VG103GA)
RT11  value 10k  [0603S]  (hidden comment: ERT-J1VG103GA)
RT12  value 10k  [0603S]  (hidden comment: ERT-J1VG103GA)
RT13  value 10k  [0603S]  (hidden comment: ERT-J1VG103GA)
RT14  value 10k  [0603S]  (hidden comment: ERT-J1VG103GA)
RT15  value 10k  [0603S]  (hidden comment: ERT-J1VG103GA)
RT16  value 10k  [0603S]  (hidden comment: ERT-J1VG103GA)
RT17  value 10k  [0603S]  (hidden comment: ERT-J1VG103GA)
RT18  value 10k  [0603S]  (hidden comment: ERT-J1VG103GA)
RT19  value 10k  [0603S]  (hidden comment: ERT-J1VG103GA)
RT20  value 10k  [0603S]  (hidden comment: ERT-J1VG103GA)
RT21  value 10k  [0603S]  (hidden comment: ERT-J1VG103GA)
RT22  value 10k  [0603S]  (hidden comment: ERT-J1VG103GA)
RT23  value 10k  [0603S]  (hidden comment: ERT-J1VG103GA)
RT24  value 10k  [0603S]  (hidden comment: ERT-J1VG103GA)
RT25  value 10k  [0603S]  (hidden comment: ERT-J1VG103GA)
RT26  value 10k  [0603S]  (hidden comment: ERT-J1VG103GA)
RT27  value 10k  [0603S]  (hidden comment: ERT-J1VG103GA)
RT28  value 10k  [0603S]  (hidden comment: ERT-J1VG103GA)
RT29  value 10k  [0603S]  (hidden comment: ERT-J1VG103GA)
RT30  value 10k  [0603S]  (hidden comment: ERT-J1VG103GA)
RT31  value 10k  [0603S]  (hidden comment: ERT-J1VG103GA)
RT32  value 10k  [0603S]  (hidden comment: ERT-J1VG103GA)
TP1  A1M_CELL16S  [Keystone5010]
TP2  A1M_CELL0S  [Keystone5011]

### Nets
A1M_CELL0S: J2.5 J2.6 J2.11 J2.12 J2.17 J2.18 J2.23 J2.24 J7.5 J7.6 J7.11 J7.12 J7.17 J7.18 J7.23 J7.24 J15.18 J15.19 R242.1 RT1.2 RT2.1 RT3.2 RT4.1 RT5.2 RT6.1 RT7.2 RT8.1 RT9.2 RT10.1 RT11.2 RT12.1 RT13.2 RT14.1 RT15.2 RT16.1 RT17.2 RT18.1 RT19.2 RT20.1 RT21.2 RT22.1 RT23.2 RT24.1 RT25.2 RT26.1 RT27.2 RT28.1 RT29.2 RT30.1 RT31.2 RT32.1 TP2.1
A1M_CELL1: J15.17 R240.1 R242.2
A1M_CELL2: J15.16 R238.1 R240.2
A1M_CELL3: J15.15 R236.1 R238.2
A1M_CELL4: J15.14 R234.1 R236.2
A1M_CELL5: J15.13 R232.1 R234.2
A1M_CELL6: J15.12 R230.1 R232.2
A1M_CELL7: J15.11 R226.1 R230.2
A1M_CELL8: J15.10 R222.1 R226.2
A1M_CELL9: J15.9 R219.1 R222.2
A1M_CELL10: J15.8 R217.1 R219.2
A1M_CELL11: J15.7 R215.1 R217.2
A1M_CELL12: J15.6 R211.1 R215.2
A1M_CELL13: J15.5 R207.1 R211.2
A1M_CELL14: J15.4 R205.1 R207.2
A1M_CELL15: J15.3 R203.1 R205.2
A1M_CELL16S: J15.1 J15.2 R203.2 TP1.1
A1N_NTC0_C: J7.1 RT17.1
A1N_NTC1_C: J7.2 RT18.2
A1N_NTC2_C: J7.3 RT19.1
A1N_NTC3_C: J7.4 RT20.2
A1N_NTC4_C: J7.7 RT21.1
A1N_NTC5_C: J7.8 RT22.2
A1N_NTC6_C: J7.9 RT23.1
A1N_NTC7_C: J7.10 RT24.2
A1N_NTC8_C: J7.13 RT25.1
A1N_NTC9_C: J7.14 RT26.2
A1N_NTC10_C: J7.15 RT27.1
A1N_NTC11_C: J7.16 RT28.2
A1N_NTC12_C: J7.19 RT29.1
A1N_NTC13_C: J7.20 RT30.2
A1N_NTC14_C: J7.21 RT31.1
A1N_NTC15_C: J7.22 RT32.2
A2N_NTC0_C: J2.1 RT1.1
A2N_NTC1_C: J2.2 RT2.2
A2N_NTC2_C: J2.3 RT3.1
A2N_NTC3_C: J2.4 RT4.2
A2N_NTC4_C: J2.7 RT5.1
A2N_NTC5_C: J2.8 RT6.2
A2N_NTC6_C: J2.9 RT7.1
A2N_NTC7_C: J2.10 RT8.2
A2N_NTC8_C: J2.13 RT9.1
A2N_NTC9_C: J2.14 RT10.2
A2N_NTC10_C: J2.15 RT11.1
A2N_NTC11_C: J2.16 RT12.2
A2N_NTC12_C: J2.19 RT13.1
A2N_NTC13_C: J2.20 RT14.2
A2N_NTC14_C: J2.21 RT15.1
A2N_NTC15_C: J2.22 RT16.2

Not connected (* = marked no-connect by the designer): J15 20*

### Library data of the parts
J2 J7 = CMP-0096812-1: 24 Position Receptacle Connector 0.100" (2.54mm) Through Hole Gold; Part Number: 61302421121; Manufacturer: Wurth Elektronik; Conn Orientation: Vertical; ContactFinish: Gold,Nickel; SizeZ_mm: 8.64mm; AEC Qualified: No; Voltage_V: 655V; Conn Gender: Female; Is Female: yes; Row_Count: 2
J15 = CMP-0075434-1: Header, 100mil, 20x1, Gold, TH; Manufacturer: Wurth Elektronik; Pitch_mm: 2.54; Cert_VDE: N; Gender: Male; Cert_CSA: Y; Current_A: 6.3A; Voltage_V: 550V; CT: False; Row_Count: 1; CNHeader: True
R203 R205 R207 R211 R215 R217 R219 R222 R226 R230 R232 R234 R236 R238 R240 R242 = CMP-0015428-3: RES, 100, 1%, 1 W, AEC-Q200 Grade 0, 2512; Manufacturer: Vishay-Dale; Value: 100; Value_Code: 100R; Power_W: 1W; VDC_V: 500V; TempCo: 100 ppm/C; SizeArea_mm2: 20.16; SizeX_mm: 6.3; SizeY_mm: 3.2; SizeZ_mm: 0.71; EIA_Code: E96; AEC Category: Q200; AEC Qualified: Y; AEC Grade: 0
RT1-RT32 = CMP-0002359-3: Thermistor NTC, 10k ohm, 2%, 0603; Manufacturer: Panasonic; TaMax_C: 125°C; SizeX_mm: 1.6; SizeY_mm: 0.8; TaMin_C: -40°C; Power_W: 100mW; SizeZ_mm: 1; SizeArea_mm2: 1.28; SizeAreaWB_mm2: 4.68; U/M: EA
TP1 = CMP-0055147-1: Test Point, Multipurpose, Red, TH; Manufacturer: Keystone; PartNumber: 5010; CNHeader: FALSE; Green_Lifecycle: Active; Green_REACh: Passed; ContactFinish: Silver; CT: TRUE
TP2 = CMP-0055148-1: Test Point, Multipurpose, Black, TH; Manufacturer: Keystone; PartNumber: 5011; CNHeader: FALSE; Green_Lifecycle: Active; Green_REACh: Passed; ContactFinish: Silver; CT: TRUE

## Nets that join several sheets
A1_GND: Transf_BMS_Communications (5 pins), Cap_BMS_Communications (5 pins), BMU_A1_Cell_Network (22 pins), BMU_A1_bq79616 (71 pins)
A2_GND: BMU_A2_Cell_Network (22 pins), BMU_A2_bq79616 (70 pins), Transf_BMS_Communications (5 pins), Cap_BMS_Communications (5 pins)
A1_BBN_CELL: BMU_A1_Cell_Network (J16.1), BMU_A1_bq79616 (R182.1)
A1_BBP_CELL: BMU_A1_Cell_Network (J16.2), BMU_A1_bq79616 (R173.1)
A1_CB0: BMU_A1_Cell_Network (5 pins), BMU_A1_bq79616 (U19.34)
A1_CB1: BMU_A1_Cell_Network (5 pins), BMU_A1_bq79616 (U19.32)
A1_CB2: BMU_A1_Cell_Network (5 pins), BMU_A1_bq79616 (U19.30)
A1_CB3: BMU_A1_Cell_Network (5 pins), BMU_A1_bq79616 (U19.28)
A1_CB4: BMU_A1_Cell_Network (5 pins), BMU_A1_bq79616 (U19.26)
A1_CB5: BMU_A1_Cell_Network (5 pins), BMU_A1_bq79616 (U19.24)
A1_CB6: BMU_A1_Cell_Network (5 pins), BMU_A1_bq79616 (U19.22)
A1_CB7: BMU_A1_Cell_Network (5 pins), BMU_A1_bq79616 (U19.20)
A1_CB8: BMU_A1_Cell_Network (5 pins), BMU_A1_bq79616 (U19.18)
A1_CB9: BMU_A1_Cell_Network (5 pins), BMU_A1_bq79616 (U19.16)
A1_CB10: BMU_A1_Cell_Network (5 pins), BMU_A1_bq79616 (U19.14)
A1_CB11: BMU_A1_Cell_Network (5 pins), BMU_A1_bq79616 (U19.12)
A1_CB12: BMU_A1_Cell_Network (5 pins), BMU_A1_bq79616 (R87.2 U19.10)
A1_CB13: BMU_A1_Cell_Network (5 pins), BMU_A1_bq79616 (R87.1 R92.2 U19.8)
A1_CB14: BMU_A1_Cell_Network (5 pins), BMU_A1_bq79616 (R92.1 R150.2 U19.6)
A1_CB15: BMU_A1_Cell_Network (5 pins), BMU_A1_bq79616 (R150.1 R154.2 U19.4)
A1_CB16: BMU_A1_Cell_Network (C191.1 R420.2 R422.2), BMU_A1_bq79616 (C162.1 R154.1 R188.2 U19.2)
A1_COMHN: Cap_BMS_Communications (C45.1 J26.2 R74.1 R78.1), BMU_A1_bq79616 (U19.42)
A1_COMHP: Cap_BMS_Communications (C44.1 J26.3 R72.1 R74.2), BMU_A1_bq79616 (U19.43)
A1_COMLN: Transf_BMS_Communications (C49.1 J29.2 R81.2 R85.2), BMU_A1_bq79616 (U19.41)
A1_COMLP: Transf_BMS_Communications (C48.1 J29.1 R85.1 R89.2), BMU_A1_bq79616 (U19.40)
A1_PWR: BMU_A1_Cell_Network (R417.1), BMU_A1_bq79616 (R152.2 R156.1)
A1_VC0: BMU_A1_Cell_Network (C219.2 C222.1 R501.2), BMU_A1_bq79616 (U19.35)
A1_VC1: BMU_A1_Cell_Network (C215.2 C219.1 R493.2), BMU_A1_bq79616 (U19.33)
A1_VC2: BMU_A1_Cell_Network (C211.2 C215.1 R483.2), BMU_A1_bq79616 (U19.31)
A1_VC3: BMU_A1_Cell_Network (C207.2 C211.1 R473.2), BMU_A1_bq79616 (U19.29)
A1_VC4: BMU_A1_Cell_Network (C203.2 C207.1 R463.2), BMU_A1_bq79616 (U19.27)
A1_VC5: BMU_A1_Cell_Network (C198.2 C203.1 R453.2), BMU_A1_bq79616 (U19.25)
A1_VC6: BMU_A1_Cell_Network (C196.2 C198.1 R443.2), BMU_A1_bq79616 (U19.23)
A1_VC7: BMU_A1_Cell_Network (C192.2 C196.1 R433.2), BMU_A1_bq79616 (U19.21)
A1_VC8: BMU_A1_Cell_Network (C192.1 C221.2 R423.2), BMU_A1_bq79616 (U19.19)
A1_VC9: BMU_A1_Cell_Network (C217.2 C221.1 R494.2), BMU_A1_bq79616 (U19.17)
A1_VC10: BMU_A1_Cell_Network (C213.2 C217.1 R484.2), BMU_A1_bq79616 (U19.15)
A1_VC11: BMU_A1_Cell_Network (C209.2 C213.1 R474.2), BMU_A1_bq79616 (U19.13)
A1_VC12: BMU_A1_Cell_Network (C205.2 C209.1 R464.2), BMU_A1_bq79616 (R10.2 U19.11)
A1_VC13: BMU_A1_Cell_Network (C200.2 C205.1 R454.2), BMU_A1_bq79616 (R10.1 R11.2 U19.9)
A1_VC14: BMU_A1_Cell_Network (C197.2 C200.1 R444.2), BMU_A1_bq79616 (R11.1 R79.2 U19.7)
A1_VC15: BMU_A1_Cell_Network (C193.2 C197.1 R434.2), BMU_A1_bq79616 (R79.1 R84.2 U19.5)
A1_VC16: BMU_A1_Cell_Network (C193.1 R424.2), BMU_A1_bq79616 (R84.1 R179.2 U19.3)
A2_BBN_CELL: BMU_A2_Cell_Network (J3.1), BMU_A2_bq79616 (R50.1)
A2_BBP_CELL: BMU_A2_Cell_Network (J3.2), BMU_A2_bq79616 (R46.1)
A2_CB0: BMU_A2_Cell_Network (5 pins), BMU_A2_bq79616 (U4.34)
A2_CB1: BMU_A2_Cell_Network (5 pins), BMU_A2_bq79616 (U4.32)
A2_CB2: BMU_A2_Cell_Network (5 pins), BMU_A2_bq79616 (U4.30)
A2_CB3: BMU_A2_Cell_Network (5 pins), BMU_A2_bq79616 (U4.28)
A2_CB4: BMU_A2_Cell_Network (5 pins), BMU_A2_bq79616 (U4.26)
A2_CB5: BMU_A2_Cell_Network (5 pins), BMU_A2_bq79616 (U4.24)
A2_CB6: BMU_A2_Cell_Network (5 pins), BMU_A2_bq79616 (U4.22)
A2_CB7: BMU_A2_Cell_Network (5 pins), BMU_A2_bq79616 (U4.20)
A2_CB8: BMU_A2_Cell_Network (5 pins), BMU_A2_bq79616 (U4.18)
A2_CB9: BMU_A2_Cell_Network (5 pins), BMU_A2_bq79616 (U4.16)
A2_CB10: BMU_A2_Cell_Network (5 pins), BMU_A2_bq79616 (U4.14)
A2_CB11: BMU_A2_Cell_Network (5 pins), BMU_A2_bq79616 (U4.12)
A2_CB12: BMU_A2_Cell_Network (5 pins), BMU_A2_bq79616 (R5.2 U4.10)
A2_CB13: BMU_A2_Cell_Network (5 pins), BMU_A2_bq79616 (R1.2 R5.1 U4.8)
A2_CB14: BMU_A2_Cell_Network (5 pins), BMU_A2_bq79616 (R1.1 R6.2 U4.6)
A2_CB15: BMU_A2_Cell_Network (5 pins), BMU_A2_bq79616 (R2.2 R6.1 U4.4)
A2_CB16: BMU_A2_Cell_Network (C6.1 R18.2 R21.2), BMU_A2_bq79616 (C13.1 R2.1 R14.2 U4.2)
A2_COMHN: BMU_A2_bq79616 (U4.42), Transf_BMS_Communications (C50.1 J28.2 R86.1 R90.1)
A2_COMHP: BMU_A2_bq79616 (U4.43), Transf_BMS_Communications (C51.1 J28.3 R82.1 R86.2)
A2_COMLN: BMU_A2_bq79616 (U4.41), Cap_BMS_Communications (C43.1 J27.1 R73.1 R75.2)
A2_COMLP: BMU_A2_bq79616 (U4.40), Cap_BMS_Communications (C42.1 J27.2 R69.2 R73.2)
A2_PWR: BMU_A2_Cell_Network (R192.1), BMU_A2_bq79616 (R25.2 R29.1)
A2_VC0: BMU_A2_Cell_Network (C80.2 C84.1 R225.2), BMU_A2_bq79616 (U4.35)
A2_VC1: BMU_A2_Cell_Network (C76.2 C80.1 R209.2), BMU_A2_bq79616 (U4.33)
A2_VC2: BMU_A2_Cell_Network (C72.2 C76.1 R193.2), BMU_A2_bq79616 (U4.31)
A2_VC3: BMU_A2_Cell_Network (C68.2 C72.1 R176.2), BMU_A2_bq79616 (U4.29)
A2_VC4: BMU_A2_Cell_Network (C64.2 C68.1 R160.2), BMU_A2_bq79616 (U4.27)
A2_VC5: BMU_A2_Cell_Network (C60.2 C64.1 R144.2), BMU_A2_bq79616 (U4.25)
A2_VC6: BMU_A2_Cell_Network (C56.2 C60.1 R128.2), BMU_A2_bq79616 (U4.23)
A2_VC7: BMU_A2_Cell_Network (C52.2 C56.1 R110.2), BMU_A2_bq79616 (U4.21)
A2_VC8: BMU_A2_Cell_Network (C52.1 C81.2 R93.2), BMU_A2_bq79616 (U4.19)
A2_VC9: BMU_A2_Cell_Network (C77.2 C81.1 R210.2), BMU_A2_bq79616 (U4.17)
A2_VC10: BMU_A2_Cell_Network (C73.2 C77.1 R194.2), BMU_A2_bq79616 (U4.15)
A2_VC11: BMU_A2_Cell_Network (C69.2 C73.1 R177.2), BMU_A2_bq79616 (U4.13)
A2_VC12: BMU_A2_Cell_Network (C65.2 C69.1 R161.2), BMU_A2_bq79616 (R3.2 U4.11)
A2_VC13: BMU_A2_Cell_Network (C61.2 C65.1 R145.2), BMU_A2_bq79616 (R3.1 R7.2 U4.9)
A2_VC14: BMU_A2_Cell_Network (C57.2 C61.1 R129.2), BMU_A2_bq79616 (R4.2 R7.1 U4.7)
A2_VC15: BMU_A2_Cell_Network (C53.2 C57.1 R111.2), BMU_A2_bq79616 (R4.1 R8.2 U4.5)
A2_VC16: BMU_A2_Cell_Network (C53.1 R94.2), BMU_A2_bq79616 (R8.1 R408.2 U4.3)

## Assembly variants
001: not fitted !PCB1 FID1 FID2 FID3 ZZ1 ZZ2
